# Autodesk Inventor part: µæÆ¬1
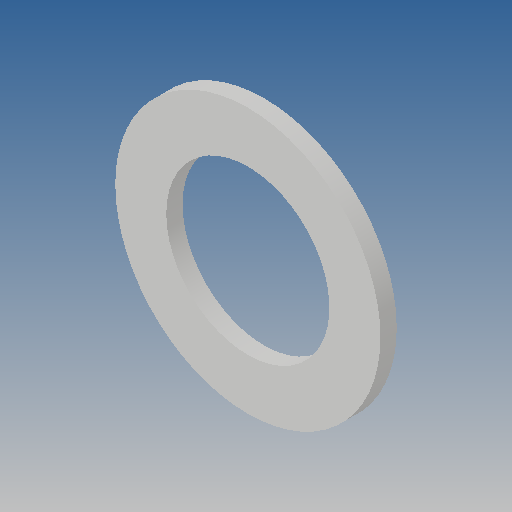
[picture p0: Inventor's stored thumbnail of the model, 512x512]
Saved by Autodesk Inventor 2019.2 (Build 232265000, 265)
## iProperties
Created: 2013-09
Part Number: µæÆ¬1
Material: Ogólny
Document SubType Name: Modeling
Designer: CADENGINEERING4
Density: 1 g/cm^3
Appearance: Domyślna
Author: CADENGINEERING4
Revision Number: ÈÎºÎ
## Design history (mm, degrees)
feature "Í¹Ì¨-À­Éì1"
node "Bryła1"
